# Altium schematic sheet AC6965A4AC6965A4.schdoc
size 127 x 101 mm
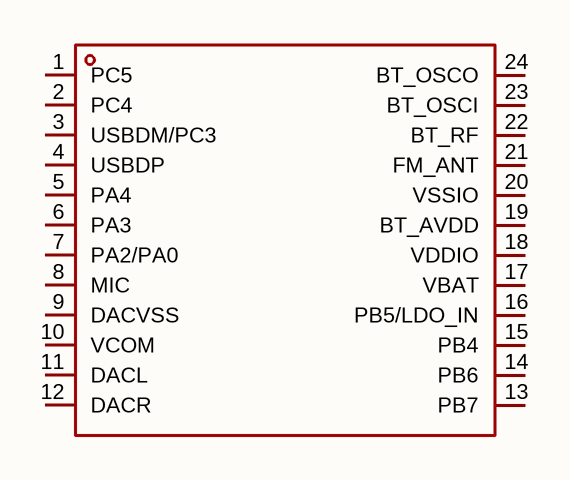
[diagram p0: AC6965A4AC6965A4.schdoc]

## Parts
U?  ac6965a4  [QSOP-24_L8.7-W3.9-P0.64-LS6.0-BL]  (value not drawn)

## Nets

Not connected (* = marked no-connect by the designer): U? 1(PC5) 2(PC4) 3(USBDM/PC3) 4(USBDP) 5(PA4) 6(PA3) 7(PA2/PA0) 8(MIC) 9(DACVSS) 10(VCOM) 11(DACL) 12(DACR) 13(PB7) 14(PB6) 15(PB4) 16(PB5/LDO_IN) 17(VBAT) 18(VDDIO) 19(BT_AVDD) 20(VSSIO) 21(FM_ANT) 22(BT_RF) 23(BT_OSCI) 24(BT_OSCO)

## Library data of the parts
U? = ac6965a4: CPU内核:-;CPU最大主频:160MHz;CPU位数:32bit;; Manufacturer: JL(杰理); AddInBom: yes; ModelId: 0d5eb4aa1e904faba2151708d4bb6535; ModelTransform: 339.369,237.007,0,0,0,0,0,0,0; CPU Maximum Speed: 160MHz; Core Size: 32bit; ADC (Bit): 16bit；10bit; DAC (Bit): 16bit; Voltage - Supply: 2.2V~5.5V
